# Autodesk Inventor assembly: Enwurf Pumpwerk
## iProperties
Created: 2005-10
Part Number: Enwurf Pumpwerk
Document SubType Name: Assembly
Designer: rsc
Manufacturer: Standard
Standards Organization: Custom
Author: rsc
